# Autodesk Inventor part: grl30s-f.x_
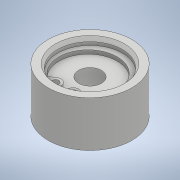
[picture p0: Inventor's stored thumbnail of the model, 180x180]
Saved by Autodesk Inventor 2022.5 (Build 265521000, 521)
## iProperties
Created: 2020-01
Part Number: grl30s-f.x_
Material: 一般
Document SubType Name: Modeling
Designer: ImaoCorp
Density: 1 g/cm^3
Appearance: 既定
Sending System: SOLIDWORKS 2018-2018316
MC: AMD64
MC_MODEL: Intel64 Family 6 Model 60 Stepping 3, GenuineIntel
OS: Windows_NT
FRU: Parasolid Version 30.0, build 310,  6- 8-2018
FORMAT: text
GUISE: transmit
KEY: grl30s-f
FILE: grl30s-f.x_t
DATE: Thu Jan 23 16:44:30 2020
Author: ImaoCorp
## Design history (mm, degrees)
feature "Base1"
node "ソリッド1"
